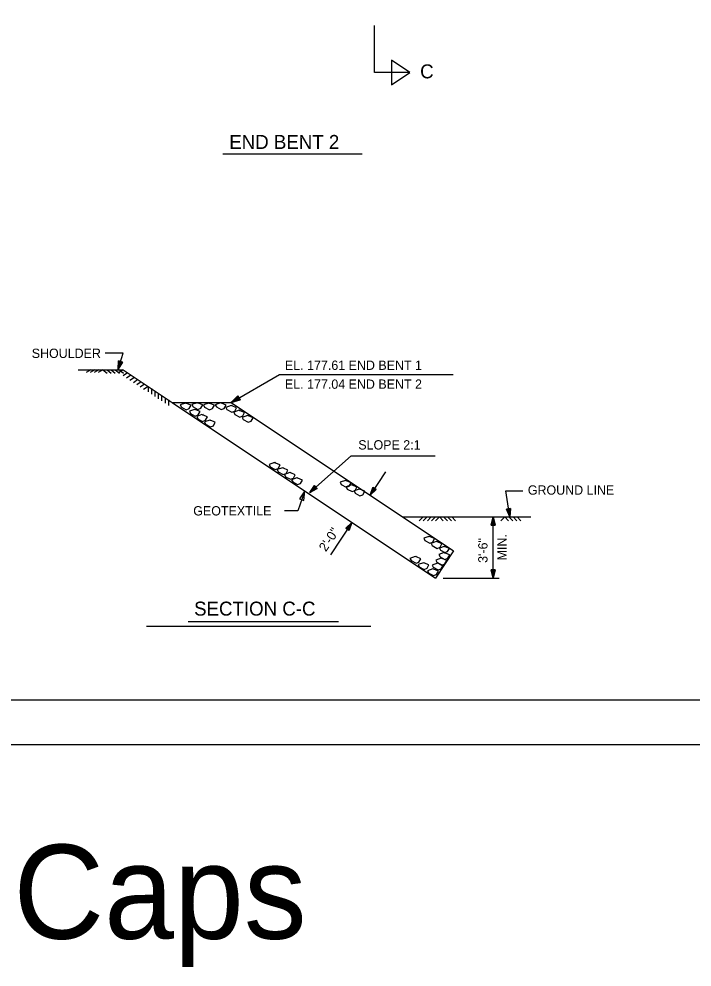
# Model space of a CAD drawing. Extents: x 0 to 265, y -200 to 22.
# Drawn here: x 119.9 to 192.2, y -199.8 to -98.1 of the extents above; entities that cross this region are included whole.
import ezdxf

# ---------------------------------------------------------------- set-up
doc = ezdxf.new("R2010")
doc.units = 0
for name, color, linetype in [('Arrowhead Terminators', 7, 'Continuous'), ('Arrowhead Terminators CELL', 7, 'Continuous'), ('Dimension Lines', 7, 'Continuous'), ('Mis Center Lines', 7, 'Continuous'), ('Mis Object Lines', 7, 'Continuous'), ('Miscellaneous Lines', 7, 'Continuous'), ('Plan Sheet', 7, 'Continuous'), ('Plot Shape', 7, 'Continuous'), ('Subtitle Text', 7, 'Continuous'), ('Text', 7, 'Continuous'), ('User Information Notes', 7, 'Continuous')]:
    doc.layers.add(name, color=color, linetype=linetype)

msp = doc.modelspace()

# ---------------------------------------------------------------- linework, layer by layer
at = {"layer": 'Arrowhead Terminators'}
msp.add_lwpolyline([(150.61, -148.74), (150.03, -149.6), (150.5, -149.76)], close=True, dxfattribs=at)
at = {"layer": 'Arrowhead Terminators CELL'}
msp.add_lwpolyline([(161.89, -103.82), (159.91, -102.5), (159.91, -105.14)], close=True, dxfattribs=at)
msp.add_lwpolyline([(161.89, -103.82), (159.91, -102.5), (159.91, -105.14)], close=True, dxfattribs=at)
at = {"layer": 'Dimension Lines'}
for p, q in [((142.68, -139.24), (147.87, -136.24)), ((147.87, -136.24), (166.54, -136.24)), ((159.28, -146.7), (157.61, -149.2)), ((170.83, -158.09), (170.83, -151.52)), ((155.67, -152.11), (153.35, -155.6)), ((165.48, -158.09), (171.47, -158.09))]:
    msp.add_line(p, q, dxfattribs=at)
for points in [[(158.1, -103.82), (158.1, -98.77)], [(161.89, -103.82), (158.1, -103.82)], [(130.55, -135.67), (131.1, -133.94), (129.17, -133.94)], [(130.81, -134.83), (130.85, -134.85), (130.55, -135.67), (130.9, -134.86), (130.94, -134.87), (130.55, -135.67), (130.98, -134.89), (131.02, -134.9), (130.55, -135.67), (130.6, -134.77), (130.65, -134.78), (130.55, -135.67), (130.69, -134.79), (130.73, -134.81), (130.55, -135.67), (130.77, -134.82), (131.02, -134.9), (130.6, -134.77), (130.55, -135.67), (131.02, -134.9)], [(143.55, -138.74), (143.57, -138.78), (142.68, -139.24), (143.6, -138.82), (143.62, -138.87), (142.68, -139.24), (143.65, -138.91), (143.67, -138.95), (142.68, -139.24), (143.42, -138.52), (143.45, -138.57), (142.68, -139.24), (143.47, -138.61), (143.5, -138.65), (142.68, -139.24), (143.52, -138.7), (143.67, -138.95), (143.42, -138.52), (142.68, -139.24), (143.67, -138.95)], [(151.14, -148.9), (155.59, -144.96), (164.62, -144.96)], [(151.8, -148.32), (151.82, -148.35), (151.14, -148.9), (151.85, -148.39), (151.88, -148.42), (151.14, -148.9), (151.91, -148.45), (151.94, -148.48), (151.14, -148.9), (151.65, -148.16), (151.68, -148.19), (151.14, -148.9), (151.71, -148.22), (151.74, -148.25), (151.14, -148.9), (151.77, -148.29), (151.94, -148.48), (151.65, -148.16), (151.14, -148.9), (151.94, -148.48)], [(158.1, -148.47), (158.13, -148.5), (157.61, -149.2), (158.17, -148.52), (158.21, -148.55), (157.61, -149.2), (158.24, -148.57), (158.28, -148.59), (157.61, -149.2), (157.91, -148.35), (157.95, -148.37), (157.61, -149.2), (157.99, -148.4), (158.02, -148.42), (157.61, -149.2), (158.06, -148.45), (158.28, -148.59), (157.91, -148.35), (157.61, -149.2), (158.28, -148.59)], [(150.61, -148.74), (149.84, -150.87), (148.43, -150.87)], [(172.64, -151.52), (172.18, -148.72), (174.02, -148.72)], [(172.5, -150.65), (172.54, -150.65), (172.64, -151.52), (172.58, -150.64), (172.63, -150.63), (172.64, -151.52), (172.67, -150.63), (172.71, -150.62), (172.64, -151.52), (172.28, -150.69), (172.33, -150.68), (172.64, -151.52), (172.37, -150.68), (172.41, -150.67), (172.64, -151.52), (172.45, -150.66), (172.71, -150.62), (172.28, -150.69), (172.64, -151.52), (172.71, -150.62)], [(170.83, -152.4), (170.78, -152.4), (170.83, -151.52), (170.74, -152.4), (170.7, -152.4), (170.83, -151.52), (170.65, -152.4), (170.61, -152.4), (170.83, -151.52), (171.05, -152.4), (171, -152.4), (170.83, -151.52), (170.96, -152.4), (170.92, -152.4), (170.83, -151.52), (170.87, -152.4), (170.61, -152.4), (171.05, -152.4), (170.83, -151.52), (170.61, -152.4)], [(155.19, -152.84), (155.15, -152.81), (155.67, -152.11), (155.11, -152.79), (155.08, -152.77), (155.67, -152.11), (155.04, -152.74), (155, -152.72), (155.67, -152.11), (155.37, -152.96), (155.33, -152.94), (155.67, -152.11), (155.3, -152.91), (155.26, -152.89), (155.67, -152.11), (155.22, -152.86), (155, -152.72), (155.37, -152.96), (155.67, -152.11), (155, -152.72)], [(170.83, -157.21), (170.87, -157.21), (170.83, -158.09), (170.92, -157.21), (170.96, -157.21), (170.83, -158.09), (171, -157.21), (171.05, -157.21), (170.83, -158.09), (170.61, -157.21), (170.65, -157.21), (170.83, -158.09), (170.7, -157.21), (170.74, -157.21), (170.83, -158.09), (170.78, -157.21), (171.05, -157.21), (170.61, -157.21), (170.83, -158.09), (171.05, -157.21)]]:
    msp.add_lwpolyline(points, dxfattribs=at)
at = {"layer": 'Mis Center Lines'}
for points in [[(137.79, -139.3), (137.22, -139.5), (137.34, -139.74), (137.87, -140.02), (138.19, -139.9), (138.39, -139.54), (137.91, -139.34), (137.91, -139.3), (137.79, -139.34)], [(139.04, -139.26), (138.48, -139.46), (138.6, -139.7), (139.12, -139.99), (139.44, -139.86), (139.64, -139.5), (139.16, -139.3), (139.16, -139.26), (139.04, -139.3)], [(140.28, -139.3), (139.72, -139.5), (139.84, -139.74), (140.36, -140.02), (140.68, -139.9), (140.89, -139.54), (140.4, -139.34), (140.4, -139.3), (140.28, -139.34)], [(141.54, -139.28), (140.98, -139.48), (141.1, -139.72), (141.62, -140), (141.94, -139.88), (142.14, -139.52), (141.66, -139.32), (141.66, -139.28), (141.54, -139.32)], [(138.76, -139.98), (138.2, -140.18), (138.32, -140.42), (138.84, -140.7), (139.16, -140.58), (139.36, -140.22), (138.88, -140.02), (138.88, -139.98), (138.76, -140.02)], [(142.68, -139.57), (142.12, -139.77), (142.24, -140.01), (142.76, -140.29), (143.08, -140.17), (143.28, -139.81), (142.8, -139.61), (142.8, -139.57), (142.68, -139.61)], [(143.54, -140.08), (142.98, -140.29), (143.1, -140.53), (143.62, -140.81), (143.94, -140.69), (144.14, -140.32), (143.66, -140.12), (143.66, -140.08), (143.54, -140.12)], [(139.55, -140.54), (138.99, -140.75), (139.11, -140.99), (139.63, -141.27), (139.95, -141.15), (140.15, -140.79), (139.67, -140.59), (139.67, -140.54), (139.55, -140.59)], [(140.39, -141.13), (139.83, -141.33), (139.95, -141.57), (140.47, -141.85), (140.79, -141.73), (140.99, -141.37), (140.51, -141.17), (140.51, -141.13), (140.39, -141.17)], [(144.43, -140.64), (143.87, -140.84), (143.99, -141.08), (144.51, -141.36), (144.83, -141.24), (145.04, -140.88), (144.55, -140.68), (144.55, -140.64), (144.43, -140.68)], [(147.34, -145.7), (146.78, -145.9), (146.9, -146.15), (147.42, -146.43), (147.74, -146.31), (147.94, -145.94), (147.46, -145.74), (147.46, -145.7), (147.34, -145.74)], [(148.19, -146.24), (147.63, -146.45), (147.75, -146.69), (148.27, -146.97), (148.59, -146.85), (148.79, -146.49), (148.31, -146.28), (148.31, -146.24), (148.19, -146.28)], [(148.98, -146.77), (148.42, -146.97), (148.54, -147.21), (149.06, -147.49), (149.38, -147.37), (149.58, -147.01), (149.1, -146.81), (149.1, -146.77), (148.98, -146.81)], [(149.75, -147.33), (149.18, -147.53), (149.3, -147.77), (149.83, -148.06), (150.15, -147.94), (150.35, -147.57), (149.87, -147.37), (149.87, -147.33), (149.75, -147.37)], [(154.97, -147.61), (154.4, -147.81), (154.52, -148.05), (155.05, -148.33), (155.37, -148.21), (155.57, -147.85), (155.09, -147.65), (155.09, -147.61), (154.97, -147.65)], [(155.61, -148.09), (155.05, -148.29), (155.17, -148.53), (155.69, -148.81), (156.01, -148.69), (156.21, -148.33), (155.73, -148.13), (155.73, -148.09), (155.61, -148.13)], [(156.45, -148.53), (155.89, -148.73), (156.01, -148.98), (156.53, -149.26), (156.85, -149.14), (157.05, -148.77), (156.57, -148.57), (156.57, -148.53), (156.45, -148.57)], [(163.94, -153.62), (163.38, -153.82), (163.5, -154.06), (164.02, -154.34), (164.34, -154.22), (164.55, -153.86), (164.06, -153.66), (164.06, -153.62), (163.94, -153.66)], [(164.73, -154.17), (164.17, -154.37), (164.29, -154.61), (164.81, -154.9), (165.13, -154.78), (165.33, -154.41), (164.85, -154.21), (164.85, -154.17), (164.73, -154.21)], [(165.58, -154.7), (165.08, -154.88), (165.19, -155.09), (165.66, -155.35), (165.94, -155.24), (166.13, -154.91), (165.69, -154.73), (165.69, -154.7), (165.58, -154.73)], [(165.57, -155.36), (165.01, -155.56), (165.13, -155.8), (165.65, -156.08), (165.97, -155.96), (166.17, -155.6), (165.69, -155.4), (165.69, -155.36), (165.57, -155.4)], [(162.47, -155.78), (161.9, -155.98), (162.03, -156.22), (162.55, -156.5), (162.87, -156.38), (163.07, -156.02), (162.59, -155.82), (162.59, -155.78), (162.47, -155.82)], [(163.34, -156.44), (162.78, -156.64), (162.9, -156.88), (163.42, -157.16), (163.74, -157.04), (163.94, -156.68), (163.46, -156.48), (163.46, -156.44), (163.34, -156.48)], [(164.84, -156.48), (164.28, -156.69), (164.4, -156.93), (164.92, -157.21), (165.25, -157.09), (165.45, -156.73), (164.96, -156.52), (164.96, -156.48), (164.84, -156.52)], [(165.25, -155.96), (164.68, -156.16), (164.8, -156.4), (165.33, -156.69), (165.65, -156.57), (165.85, -156.2), (165.37, -156), (165.37, -155.96), (165.25, -156)], [(164.35, -157.11), (163.79, -157.31), (163.91, -157.55), (164.43, -157.83), (164.76, -157.71), (164.96, -157.35), (164.47, -157.15), (164.47, -157.11), (164.35, -157.15)]]:
    msp.add_lwpolyline(points, dxfattribs=at)
at = {"layer": 'Mis Object Lines'}
for p, q in [((127.61, -135.73), (127.1, -136.02)), ((128.04, -135.73), (127.53, -136.02)), ((128.48, -135.73), (127.97, -136.02)), ((128.92, -135.73), (128.41, -136.02)), ((128.92, -135.73), (129.37, -136.1)), ((129.36, -135.73), (129.81, -136.1)), ((129.8, -135.73), (130.25, -136.1)), ((130.24, -135.73), (130.69, -136.1)), ((131.08, -135.73), (130.6, -136.06)), ((130.68, -135.73), (131.13, -136.1)), ((131.57, -136.05), (131.09, -136.39)), ((131.93, -136.29), (131.45, -136.63)), ((132.3, -136.54), (131.82, -136.87)), ((132.66, -136.78), (132.19, -137.12)), ((133.03, -137.02), (132.55, -137.36)), ((133.39, -137.27), (132.92, -137.6)), ((133.76, -137.51), (133.28, -137.85)), ((133.76, -137.51), (133.76, -138.1)), ((134.12, -137.75), (134.12, -138.34)), ((134.49, -138), (134.49, -138.58)), ((134.86, -138.24), (134.86, -138.83)), ((135.22, -138.49), (135.22, -139.07)), ((135.59, -138.73), (135.59, -139.31)), ((135.95, -138.97), (135.95, -139.56)), ((161.11, -151.52), (168.41, -151.52)), ((163.31, -151.52), (162.89, -151.94)), ((163.75, -151.52), (163.33, -151.94)), ((164.19, -151.52), (163.77, -151.94)), ((164.63, -151.52), (164.21, -151.94)), ((165.06, -151.52), (164.65, -151.94)), ((165.06, -151.52), (165.48, -151.94)), ((165.5, -151.52), (165.92, -151.94)), ((165.94, -151.52), (166.36, -151.94)), ((166.38, -151.52), (166.79, -151.94)), ((168.41, -151.52), (174.89, -151.52)), ((172.09, -151.52), (171.67, -151.94)), ((172.09, -151.52), (172.5, -151.94)), ((172.53, -151.52), (172.94, -151.94)), ((172.97, -151.52), (173.38, -151.94)), ((173.4, -151.52), (173.82, -151.94))]:
    msp.add_line(p, q, dxfattribs=at)
at = {"layer": 'Miscellaneous Lines'}
for p, q in [((126.25, -135.72), (131.08, -135.72)), ((131.08, -135.72), (136.35, -139.24)), ((136.35, -139.24), (142.68, -139.24)), ((136.35, -139.24), (164.63, -158.09)), ((142.68, -139.24), (166.57, -155.16)), ((166.57, -155.16), (164.63, -158.09))]:
    msp.add_line(p, q, dxfattribs=at)
at = {"layer": 'Plan Sheet'}
msp.add_line((8.43, -171.15), (264.44, -171.15), dxfattribs=at)
at = {"layer": 'Plot Shape'}
msp.add_lwpolyline([(0, 0), (264.51, 0), (264.51, -176), (0, -176)], close=True, dxfattribs=at)
at = {"layer": 'Subtitle Text'}
msp.add_line((141.8, -112.55), (156.77, -112.55), dxfattribs=at)
at = {"layer": 'Text'}
for p, q in [((138.09, -162.75), (154.22, -162.75)), ((133.59, -163.25), (157.7, -163.25))]:
    msp.add_line(p, q, dxfattribs=at)

# ---------------------------------------------------------------- texts
at = {"layer": 'Subtitle Text'}
for s, p in [('C', (162.99, -104.44)), ('END BENT 2', (142.49, -112.02))]:
    msp.add_text(s, height=1.5, dxfattribs=at).set_placement(p)
at = {"layer": 'Text'}
for s, height, p in [('SHOULDER', 1, (121.27, -134.46)), ('EL. 177.61 END BENT 1 ', 1, (148.47, -135.74)), ('EL. 177.04 END BENT 2 ', 1, (148.47, -137.77)), ('SLOPE 2:1', 1, (156.35, -144.29)), ('GROUND LINE', 1, (174.56, -149.14)), ('GEOTEXTILE', 1, (138.62, -151.37)), ('SECTION C-C', 1.5, (138.71, -162.12))]:
    msp.add_text(s, height=height, dxfattribs=at).set_placement(p)
for s, rotation, p in [('2\'-0"', 56.3105, (152.87, -155.33)), ('MIN.', 90, (172.28, -156.19)), ('3\'-6"', 90, (170.23, -156.46))]:
    msp.add_text(s, height=1, rotation=rotation, dxfattribs=at).set_placement(p)
at = {"layer": 'User Information Notes'}
msp.add_text('4\'-0" deep EB Caps', height=10.0915, dxfattribs=at).set_placement((33.16, -196.81))

doc.saveas('drawing.dxf')
